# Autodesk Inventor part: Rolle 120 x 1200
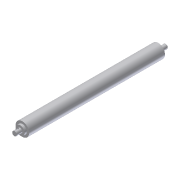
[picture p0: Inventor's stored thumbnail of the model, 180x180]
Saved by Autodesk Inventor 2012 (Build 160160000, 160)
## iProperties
Created: 2004-04
Part Number: Rolle 120 x 1200
Document SubType Name: Modeling
Manufacturer: Standard
Standards Organization: Custom
Description: Welle
Density: 1 g/cm^3
Material: Standard
Company: CAD-Verlag
+MSCProtocol1+ProtocolID: P00061127083254156
+MSCProtocol2+Protocol: P00061127083254156<@PID>[Version]<@EL>Version=2.0<@EL>[Mechsoft]<@EL>Dynamic=1<@EL>[Synchronize]<@EL>ChangedVars=<@EL>[Debug]<@EL>ChangedVars=<@EL>[Files]<@EL>D
Author: Jürgen Kronas
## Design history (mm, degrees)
sketch "Skizze2"
  geometry: L1 (0, 0)-(1335, 0) reference; L2 (0, 0)-(0, 20); L3 (0, 20)-(50, 20); L4 (50, 20)-(50, 40); L5 (50, 40)-(70, 40); L6 (70, 40)-(70, 60); L7 (1270, 60)-(1270, 40); L8 (70, 60)-(1270, 60); L9 (1285, 40)-(1285, 20); L10 (1270, 40)-(1285, 40); L11 (1335, 20)-(1335, 0); L12 (1285, 20)-(1335, 20)
  constraints: 24 end point, 6 vertical, 2 horizontal
  dimensions: "d0" = 40 diameter of L3 L1 (derived); "d1" = 80 diameter of L5 L1 (derived); "d2" = 120 diameter of L8 L1 (derived); "d3" = 80 diameter of L10 L1 (derived); "d4" = 40 diameter of L12 L1 (derived)
revolve "Drehung1" sketch "Skizze2" stored, may be unused: angle "d5" = 0 deg
feature "Keyway1"
feature "RRGroove1"
node "Volumenkörper1"
node "Volumenkörpern"
node "Oberflächenkörpern"
